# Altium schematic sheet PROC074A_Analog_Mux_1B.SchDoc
size 431 x 279 mm; Date: Not shown in title block; ApprovedBy: Not shown in title block; CheckedBy: Not shown in title block; Author: Not shown in title block; CompanyName: Not shown in title block; Engineer: Not shown in title block; Organization: Not shown in title block; Address1: Not shown in title block; Address2: Not shown in title block; Address3: Not shown in title block; Address4: Not shown in title block; DocumentNumber: 1; Revision: Use project parameter SCH_Rev; SheetNumber: 20; SheetTotal: 22; PageSetup: Record=PageOptions¦CenterHorizontal=True¦CenterVertical=True¦PrintScale=1.00¦XCorrection=1.00¦YCorrection=1.00¦PrintKind=0¦BorderSize=5000000¦LeftOffset=0¦BottomOffset=0¦Orientation=2¦PaperLength=1000¦PaperWidth=1000¦Scale=100¦PaperSource=15¦PrintQuality=600¦MediaType=1¦DitherType=10¦PaperKind=Letter¦PrintScaleMode=1
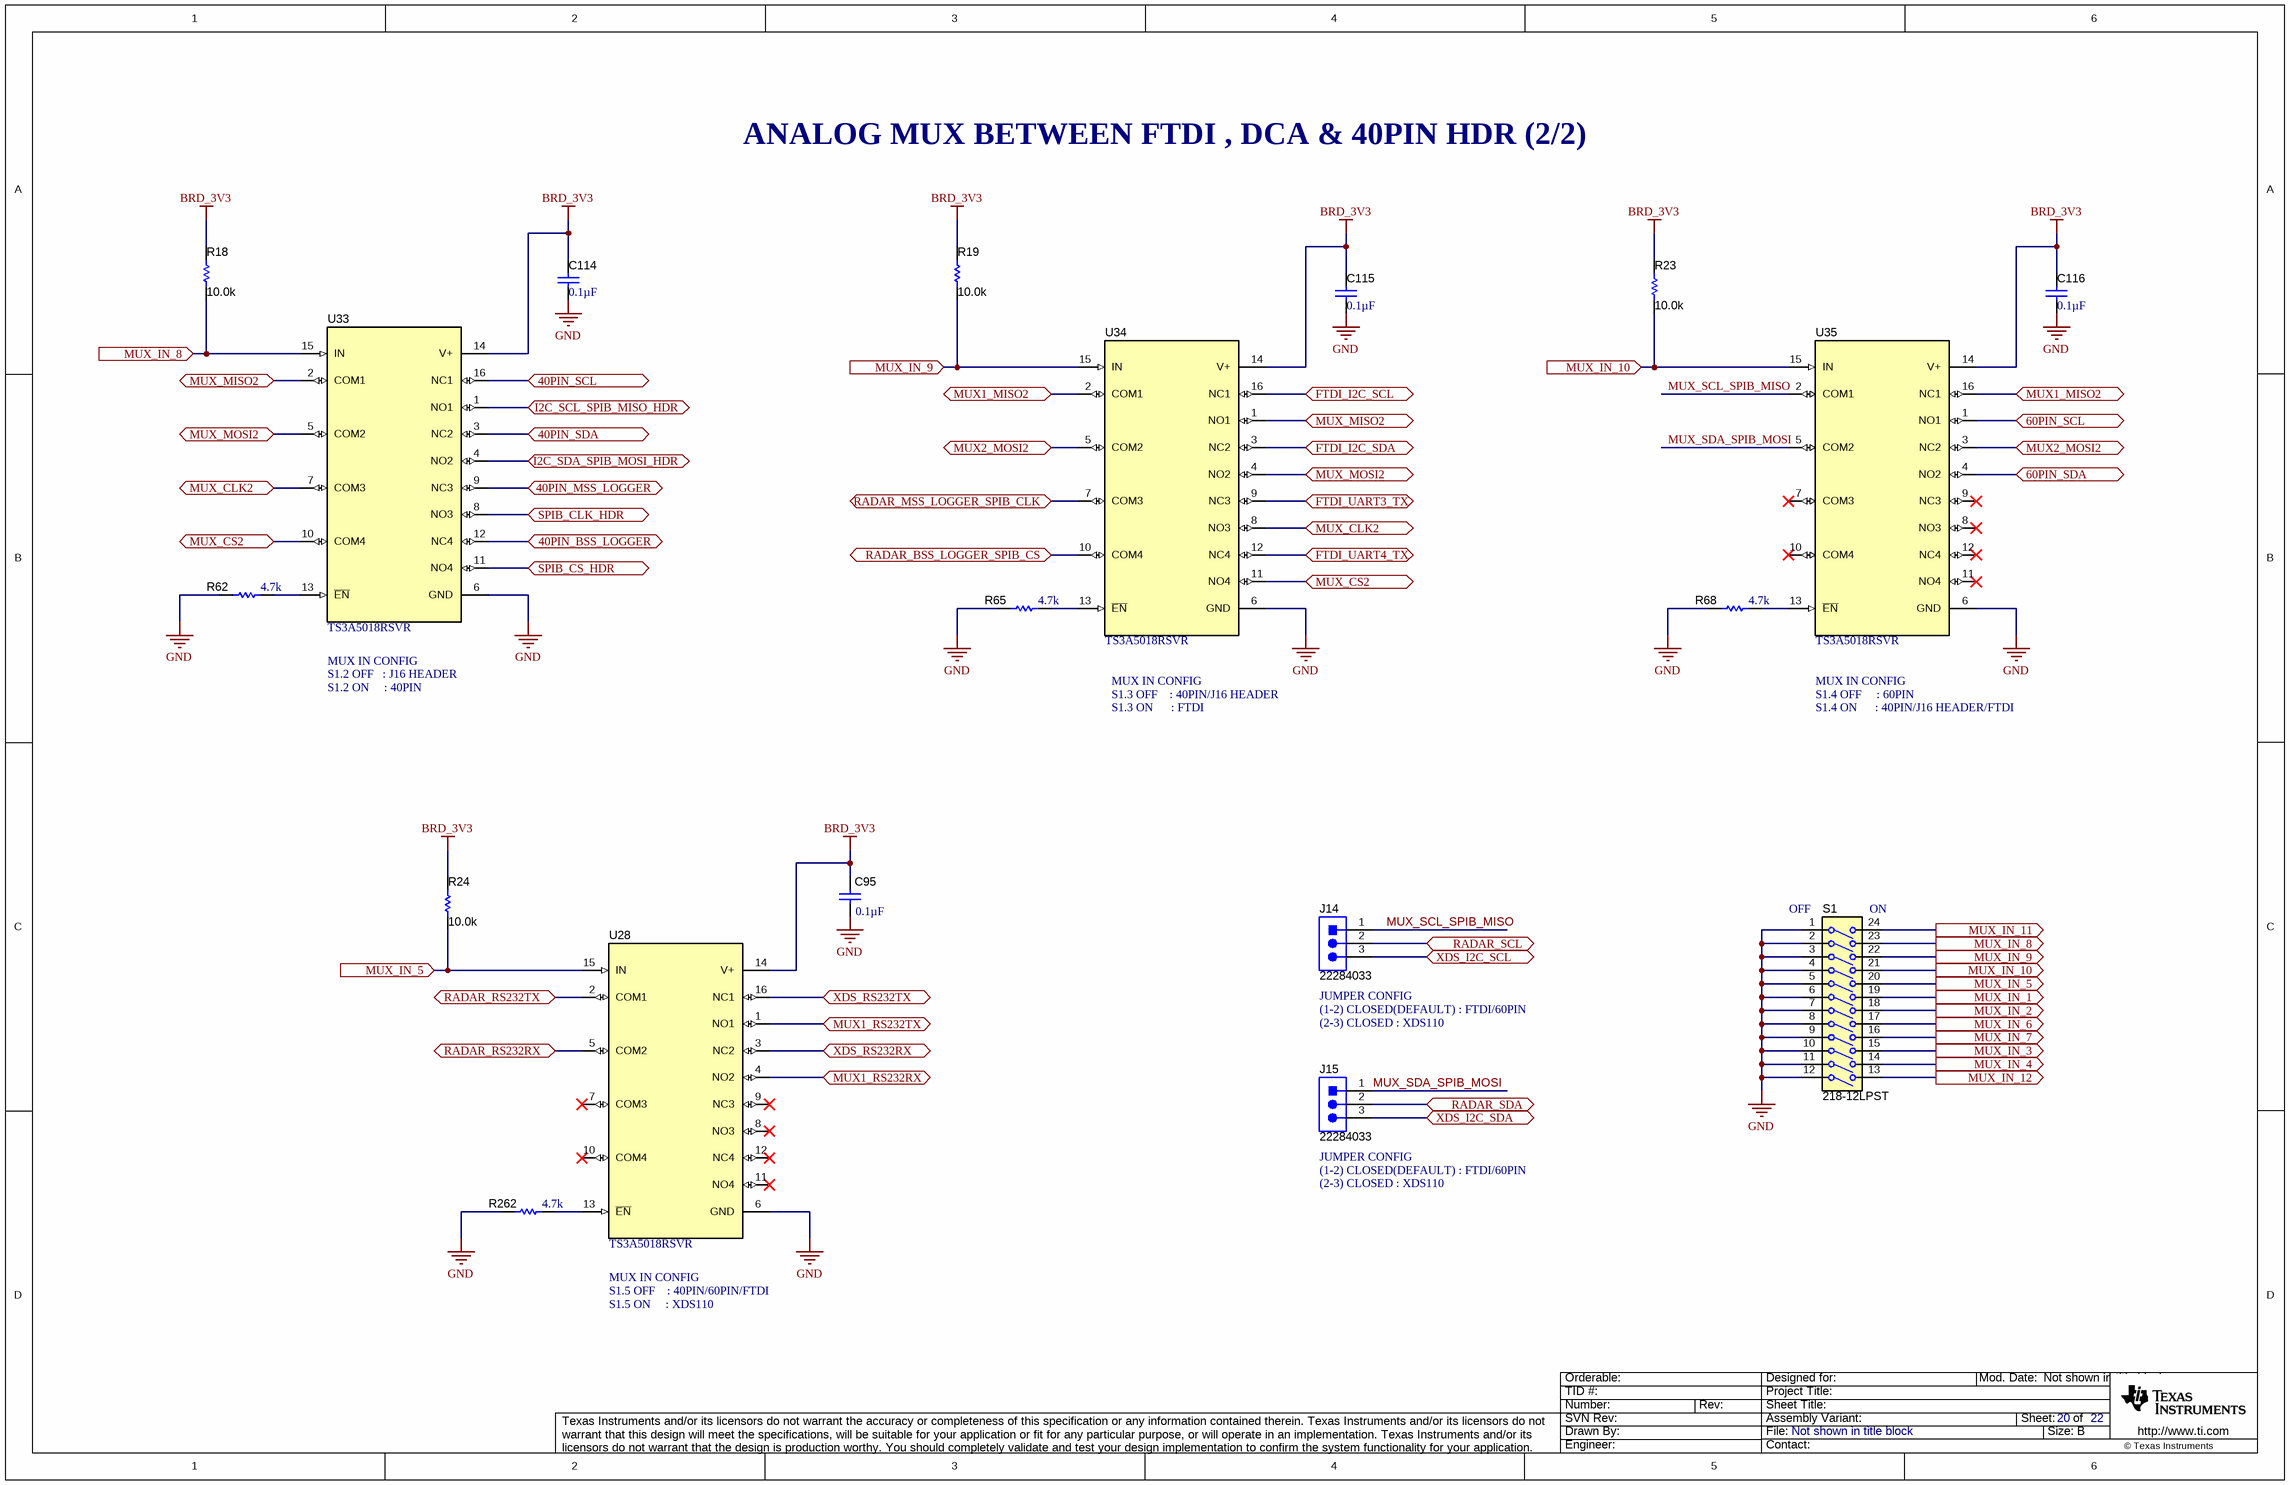
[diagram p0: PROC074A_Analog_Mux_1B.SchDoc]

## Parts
C95  ValueDisplayed: 0.1µF  [0402]  (hidden comment: C0402C104K8RACTU)
C114  ValueDisplayed: 0.1µF  [0402]  (hidden comment: C0402C104K8RACTU)
C115  ValueDisplayed: 0.1µF  [0402]  (hidden comment: C0402C104K8RACTU)
C116  ValueDisplayed: 0.1µF  [0402]  (hidden comment: C0402C104K8RACTU)
J14  22284033  [Molex_0022284033]
J15  22284033  [Molex_0022284033]
R18  ValueDisplayed: 10.0k  [0402L]  (hidden comment: CRCW040210K0FKED)
R19  ValueDisplayed: 10.0k  [0402L]  (hidden comment: CRCW040210K0FKED)
R23  ValueDisplayed: 10.0k  [0402L]  (hidden comment: CRCW040210K0FKED)
R24  ValueDisplayed: 10.0k  [0402L]  (hidden comment: CRCW040210K0FKED)
R62  ValueDisplayed: 4.7k  [0402]  (hidden comment: CRCW04024K70JNED)
R65  ValueDisplayed: 4.7k  [0402]  (hidden comment: CRCW04024K70JNED)
R68  ValueDisplayed: 4.7k  [0402]  (hidden comment: CRCW04024K70JNED)
R262  ValueDisplayed: 4.7k  [0402]  (hidden comment: CRCW04024K70JNED)
S1  218-12LPST  [SW_218-12LPST]
U28  TS3A5018RSVR  [RSV0016A]
U33  TS3A5018RSVR  [RSV0016A]
U34  TS3A5018RSVR  [RSV0016A]
U35  TS3A5018RSVR  [RSV0016A]

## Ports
40PIN_BSS_LOGGER, 40PIN_MSS_LOGGER, 40PIN_SCL, 40PIN_SDA, 60PIN_SCL, 60PIN_SDA, FTDI_I2C_SCL, FTDI_I2C_SDA, FTDI_UART3_TX, FTDI_UART4_TX, I2C_SCL_SPIB_MISO_HDR, I2C_SDA_SPIB_MOSI_HDR, MUX1_MISO2, MUX1_RS232RX, MUX1_RS232TX, MUX2_MOSI2, MUX_CLK2, MUX_CS2, MUX_IN_1 (out), MUX_IN_2 (out), MUX_IN_3 (out), MUX_IN_4 (out), MUX_IN_5 (in), MUX_IN_5 (out), MUX_IN_6 (out), MUX_IN_7 (out), MUX_IN_8 (in), MUX_IN_8 (out), MUX_IN_9 (in), MUX_IN_9 (out), MUX_IN_10 (in), MUX_IN_10 (out), MUX_IN_11 (out), MUX_IN_12 (out), MUX_MISO2, MUX_MOSI2, RADAR_BSS_LOGGER_SPIB_CS, RADAR_MSS_LOGGER_SPIB_CLK, RADAR_RS232RX, RADAR_RS232TX, RADAR_SCL, RADAR_SDA, SPIB_CLK_HDR, SPIB_CS_HDR, XDS_I2C_SCL, XDS_I2C_SDA, XDS_RS232RX, XDS_RS232TX

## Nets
BRD_3V3: C95.1 C114.1 C115.1 C116.1 R18.2 R19.2 R23.2 R24.2 U28.14(V+) U33.14(V+) U34.14(V+) U35.14(V+)
GND: C95.2 C114.2 C115.2 C116.2 R62.1 R65.1 R68.1 R262.1 S1.1 S1.2 S1.3 S1.4 S1.5 S1.6 S1.7 S1.8 S1.9 S1.10 S1.11 S1.12 U28.6(GND) U33.6(GND) U34.6(GND) U35.6(GND)
40PIN_BSS_LOGGER: U33.12(NC4) ; port 40PIN_BSS_LOGGER
40PIN_MSS_LOGGER: U33.9(NC3) ; port 40PIN_MSS_LOGGER
40PIN_SCL: U33.16(NC1) ; port 40PIN_SCL
40PIN_SDA: U33.3(NC2) ; port 40PIN_SDA
60PIN_SCL: U35.1(NO1) ; port 60PIN_SCL
60PIN_SDA: U35.4(NO2) ; port 60PIN_SDA
FTDI_I2C_SCL: U34.16(NC1) ; port FTDI_I2C_SCL
FTDI_I2C_SDA: U34.3(NC2) ; port FTDI_I2C_SDA
FTDI_UART3_TX: U34.9(NC3) ; port FTDI_UART3_TX
FTDI_UART4_TX: U34.12(NC4) ; port FTDI_UART4_TX
I2C_SCL_SPIB_MISO_HDR: U33.1(NO1) ; port I2C_SCL_SPIB_MISO_HDR
I2C_SDA_SPIB_MOSI_HDR: U33.4(NO2) ; port I2C_SDA_SPIB_MOSI_HDR
MUX1_MISO2: U34.2(COM1) U35.16(NC1) ; port MUX1_MISO2
MUX1_RS232RX: U28.4(NO2) ; port MUX1_RS232RX
MUX1_RS232TX: U28.1(NO1) ; port MUX1_RS232TX
MUX2_MOSI2: U34.5(COM2) U35.3(NC2) ; port MUX2_MOSI2
MUX_CLK2: U33.7(COM3) U34.8(NO3) ; port MUX_CLK2
MUX_CS2: U33.10(COM4) U34.11(NO4) ; port MUX_CS2
MUX_IN_1: S1.19 ; port MUX_IN_1
MUX_IN_2: S1.18 ; port MUX_IN_2
MUX_IN_3: S1.15 ; port MUX_IN_3
MUX_IN_4: S1.14 ; port MUX_IN_4
MUX_IN_5: R24.1 S1.20 U28.15(IN) ; port MUX_IN_5
MUX_IN_6: S1.17 ; port MUX_IN_6
MUX_IN_7: S1.16 ; port MUX_IN_7
MUX_IN_8: R18.1 S1.23 U33.15(IN) ; port MUX_IN_8
MUX_IN_9: R19.1 S1.22 U34.15(IN) ; port MUX_IN_9
MUX_IN_10: R23.1 S1.21 U35.15(IN) ; port MUX_IN_10
MUX_IN_11: S1.24 ; port MUX_IN_11
MUX_IN_12: S1.13 ; port MUX_IN_12
MUX_MISO2: U33.2(COM1) U34.1(NO1) ; port MUX_MISO2
MUX_MOSI2: U33.5(COM2) U34.4(NO2) ; port MUX_MOSI2
MUX_SCL_SPIB_MISO: J14.1 U35.2(COM1)
MUX_SDA_SPIB_MOSI: J15.1 U35.5(COM2)
RADAR_BSS_LOGGER_SPIB_CS: U34.10(COM4) ; port RADAR_BSS_LOGGER_SPIB_CS
RADAR_MSS_LOGGER_SPIB_CLK: U34.7(COM3) ; port RADAR_MSS_LOGGER_SPIB_CLK
RADAR_RS232RX: U28.5(COM2) ; port RADAR_RS232RX
RADAR_RS232TX: U28.2(COM1) ; port RADAR_RS232TX
RADAR_SCL: J14.2 ; port RADAR_SCL
RADAR_SDA: J15.2 ; port RADAR_SDA
SPIB_CLK_HDR: U33.8(NO3) ; port SPIB_CLK_HDR
SPIB_CS_HDR: U33.11(NO4) ; port SPIB_CS_HDR
XDS_I2C_SCL: J14.3 ; port XDS_I2C_SCL
XDS_I2C_SDA: J15.3 ; port XDS_I2C_SDA
XDS_RS232RX: U28.3(NC2) ; port XDS_RS232RX
XDS_RS232TX: U28.16(NC1) ; port XDS_RS232TX
NetR62_2: R62.2 U33.13(~{EN})
NetR65_2: R65.2 U34.13(~{EN})
NetR68_2: R68.2 U35.13(~{EN})
NetR262_2: R262.2 U28.13(~{EN})

Not connected (* = marked no-connect by the designer): U28 7(COM3)* 8(NO3)* 9(NC3)* 10(COM4)* 11(NO4)* 12(NC4)*; U35 7(COM3)* 8(NO3)* 9(NC3)* 10(COM4)* 11(NO4)* 12(NC4)*

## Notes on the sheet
- ANALOG MUX BETWEEN FTDI , DCA & 40PIN HDR (2/2)
- MUX IN CONFIG
- S1.2 OFF   : J16 HEADER
- S1.2 ON     : 40PIN
- S1.3 OFF    : 40PIN/J16 HEADER
- S1.4 OFF     : 60PIN
- S1.3 ON      : FTDI
- S1.4 ON      : 40PIN/J16 HEADER/FTDI
- (near S1) OFF
- (near S1) ON
- (near J14) JUMPER CONFIG
- (1-2) CLOSED(DEFAULT) : FTDI/60PIN
- (2-3) CLOSED : XDS110
- (near J15) JUMPER CONFIG
- (near J15) (1-2) CLOSED(DEFAULT) : FTDI/60PIN
- S1.5 OFF    : 40PIN/60PIN/FTDI
- S1.5 ON     : XDS110

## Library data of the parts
C95 C114-C116 = CMP-0078241-1: CAP, CERM, 0.1 µF, 10 V,+/- 10%, X7R, 0402; Manufacturer: Kemet; TaMin_C: -55°C; Polarized: N; SizeAreaWB_mm2: 3; U/M: EA; Value: 0.1uF; TaMax_C: 125°C; SizeZ_mm: 0.6; SizeX_mm: 1; SizeY_mm: 0.5; Value2: 10V; CompType: Capacitor; Cap_F: 100nF; AEC Category: Q200
J14 J15 = CMP-0055332-1: Header, 2.54mm, 3x1, Tin, TH; Manufacturer: Molex; CNHeader: TRUE; Current_A: 4A; Shrouded: N; Gender: Male; Voltage_V: 250V; Row_Count: 1; Pitch_mm: 2.54; CT: FALSE; Cert_UL: Y
R18 R19 R23 R24 = CMP-0025958-2: RES, 10.0 k, 1%, 0.063 W, 0402; Manufacturer: Vishay-Dale; Power_W: 63mW; TempCo: 100 ppm/C; Value_Code: 10k0; U/M: EA; Value: 10.0k; EIA_Code: E96; Res_ohm: 10k; SizeX_mm: 1; SizeY_mm: 0.5; SizeZ_mm: 0.6; Value2: 0.063W; VDC_V: 50V; AEC Category: Q200
R62 R65 R68 R262 = CMP-0026938-5: RES, 4.7 k, 5%, 0.063 W, AEC-Q200 Grade 0, 0402; Manufacturer: Vishay-Dale; Power_W: 63mW; TempCo: 200 ppm/C; Value_Code: 4k70; Value: 4.7k; EIA_Code: E24; SizeX_mm: 1; SizeY_mm: 0.5; SizeZ_mm: 0.6; Value2: 0.063W; AEC Qualified: Y; VDC_V: 50V; AEC Category: Q200; AEC Grade: 0
S1 = CMP-0084286-2: Switch, SPST, 12 Pos, 0.025 A, 24 VDC, SMD; Manufacturer: CTS Electrocomponents; SizeY_mm: 16.41; SizeArea_mm2: 138.5004; SizeX_mm: 8.44; CurrentRating_mA: 25A; VDC_V: 24V; SwitchFunction: Off-On; SizeZ_mm: 2.65; PositionCount: 12; SizeAreaWB_mm2: 192.2004
U28 U33-U35 = CMP-0067415-1: 10-Ohm Quad SPDT Analog Switch, RSV0016A (UQFN-16); Alternate Manufacturer: Texas Instruments; SizeAreaWB_mm2: 10.08; U/M: EA; SizeZ_mm: 0.55; SizeX_mm: 1.8; SizeY_mm: 2.6; SizeArea_mm2: 4.68; CompType: IC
